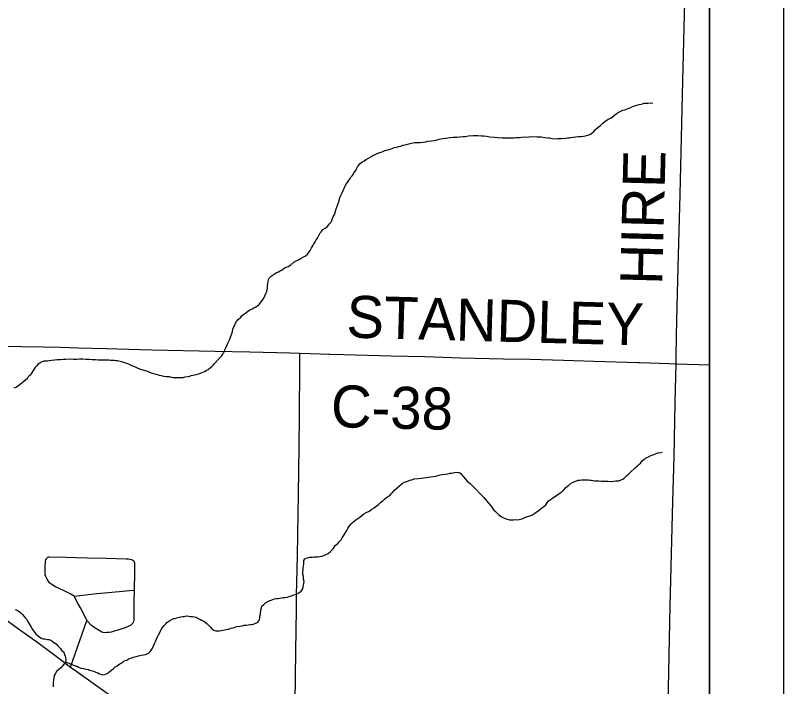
# Model space of a CAD drawing. Extents: x 0 to 34, y 0 to 22.
# Drawn here: x 29.379 to 30.417, y 16.904 to 17.811 of the extents above; entities that cross this region are included whole.
import ezdxf

# ---------------------------------------------------------------- set-up
doc = ezdxf.new("R2010")
doc.units = 0
for name, color, linetype in [('GM_X_City_Street', 7, 'Continuous'), ('GM_X_County_Road', 7, 'Continuous'), ('GM_X_County_Road_Text', 7, 'Continuous'), ('GM_X_Minor_River', 7, 'Continuous'), ('GM_X_Township_Road', 7, 'Continuous'), ('SH_Data', 7, 'Continuous')]:
    doc.layers.add(name, color=color, linetype=linetype)

msp = doc.modelspace()

# ---------------------------------------------------------------- linework, layer by layer
at = {"layer": 'GM_X_City_Street'}
for points in [[(29.4539, 16.9309), (29.4761, 16.9936), (29.4717, 17.0021), (29.4672, 17.0107), (29.4644, 17.0161), (29.459, 17.0266), (29.4533, 17.0298), (29.4461, 17.0334), (29.4388, 17.0369), (29.4338, 17.0393), (29.43, 17.0413), (29.4279, 17.0426), (29.4256, 17.0447), (29.4237, 17.0472), (29.4218, 17.0504), (29.4205, 17.0532), (29.4199, 17.0556), (29.4195, 17.0586), (29.4196, 17.0635), (29.4198, 17.068), (29.42, 17.0716), (29.4202, 17.074), (29.4207, 17.0757), (29.4213, 17.0769), (29.4219, 17.0777), (29.4226, 17.0784), (29.4235, 17.0791), (29.4244, 17.0795), (29.4254, 17.0796), (29.4475, 17.0793), (29.4762, 17.0785), (29.5022, 17.0778), (29.5292, 17.0771), (29.5318, 17.077), (29.5343, 17.0767), (29.5364, 17.0762), (29.5382, 17.0753), (29.5392, 17.0743), (29.5397, 17.0731), (29.5401, 17.0716), (29.5403, 17.0692), (29.5404, 17.065), (29.5403, 17.0566), (29.5402, 17.0508), (29.5399, 17.0431), (29.5398, 17.0379), (29.5397, 17.0346), (29.5397, 17.03), (29.5396, 17.0226), (29.5395, 17.0108), (29.5395, 17.004), (29.5394, 16.9965), (29.5392, 16.9934), (29.5387, 16.9916), (29.5379, 16.99), (29.5366, 16.9886), (29.5352, 16.9874), (29.5319, 16.9856), (29.5265, 16.9832), (29.5217, 16.9818), (29.519, 16.981), (29.5163, 16.9801), (29.5127, 16.9792), (29.509, 16.9781), (29.506, 16.9775), (29.5029, 16.9773), (29.4999, 16.9772), (29.4961, 16.9781), (29.4924, 16.9801), (29.4874, 16.9833), (29.4822, 16.987), (29.4761, 16.9936)], [(29.459, 17.0266), (29.4896, 17.0302), (29.5048, 17.0315), (29.5198, 17.033), (29.5334, 17.0341), (29.5397, 17.0346)]]:
    msp.add_lwpolyline(points, dxfattribs=at)
at = {"layer": 'GM_X_County_Road'}
for p, q in [((30.2714, 17.3404), (30.3167, 17.3391)), ((29.4539, 16.9309), (29.4623, 16.9248))]:
    msp.add_line(p, q, dxfattribs=at)
for points in [[(30.2714, 17.3404), (30.2716, 17.3482), (30.2721, 17.3787), (30.273, 17.4172), (30.2745, 17.4707), (30.2772, 17.5689), (30.2807, 17.7224), (30.283, 17.812), (30.2857, 17.9089), (30.2857, 17.9102), (30.2858, 17.9114), (30.287, 17.9667), (30.2885, 18.0102), (30.2894, 18.0531), (30.2902, 18.0898), (30.2911, 18.1296), (30.2925, 18.1812), (30.2935, 18.2184), (30.2939, 18.2503), (30.2938, 18.2543)], [(29.2614, 17.3664), (29.2894, 17.3655), (29.3043, 17.3651), (29.3229, 17.3648), (29.3362, 17.3646), (29.3679, 17.3641), (29.3883, 17.3637), (29.4168, 17.3634), (29.4405, 17.363), (29.4649, 17.3621), (29.502, 17.3612), (29.5635, 17.3593), (29.6487, 17.3575), (29.696, 17.3563), (29.7498, 17.355), (29.7636, 17.3547)], [(29.7636, 17.3547), (29.7912, 17.3538), (29.803, 17.3535), (29.804, 17.3535)], [(29.804, 17.3535), (29.8229, 17.3531), (29.8863, 17.3512), (29.9323, 17.3503), (29.9808, 17.3486), (30.0386, 17.3472), (30.0746, 17.3465), (30.1194, 17.3452), (30.1604, 17.3441), (30.2203, 17.3422), (30.2219, 17.3421), (30.2623, 17.3407), (30.2714, 17.3404)], [(29.2601, 17.0722), (29.2755, 17.0612), (29.298, 17.0446), (29.3449, 17.0108), (29.3616, 16.9987), (29.3837, 16.9826), (29.41, 16.9638), (29.4364, 16.9441), (29.4539, 16.9309)], [(29.4623, 16.9248), (29.5064, 16.8932), (29.5256, 16.8784), (29.5445, 16.8643), (29.5651, 16.8492), (29.5791, 16.839), (29.5943, 16.8281), (29.6104, 16.8163)]]:
    msp.add_lwpolyline(points, dxfattribs=at)
at = {"layer": 'GM_X_Minor_River'}
for points in [[(29.8653, 17.6232), (29.868, 17.6243), (29.8715, 17.6257), (29.8745, 17.6268), (29.8784, 17.6282), (29.8841, 17.6299), (29.888, 17.6313), (29.891, 17.6324), (29.8941, 17.633), (29.8972, 17.6337), (29.8998, 17.6344), (29.9025, 17.6355), (29.9052, 17.6361), (29.9075, 17.6365), (29.9106, 17.6375), (29.9144, 17.6382), (29.9182, 17.6392), (29.9231, 17.639), (29.9258, 17.6393), (29.9334, 17.6403), (29.9361, 17.6409), (29.9414, 17.6416), (29.9449, 17.6418), (29.9475, 17.6425), (29.9514, 17.6435), (29.9567, 17.6445), (29.9605, 17.6452), (29.9632, 17.6455), (29.9666, 17.6461), (29.9704, 17.6464), (29.9735, 17.6463), (29.9758, 17.6466), (29.9792, 17.6469), (29.9841, 17.6472), (29.9868, 17.6475), (29.991, 17.6481), (29.9975, 17.6487), (30.0036, 17.6485), (30.0081, 17.6484), (30.0119, 17.6482), (30.0153, 17.6478), (30.0198, 17.6469), (30.0259, 17.6463), (30.0308, 17.6458), (30.0365, 17.6456), (30.0411, 17.6455), (30.0464, 17.6453), (30.0502, 17.6456), (30.0528, 17.6455), (30.0551, 17.6458), (30.0578, 17.6461), (30.0605, 17.6461), (30.0627, 17.6464), (30.0662, 17.6467), (30.0704, 17.6465), (30.0749, 17.6472), (30.0833, 17.6469), (30.0893, 17.6468), (30.0943, 17.6458), (30.0981, 17.6457), (30.1007, 17.6453), (30.1041, 17.6448), (30.1075, 17.6443), (30.1113, 17.6446), (30.1166, 17.6448), (30.122, 17.645), (30.125, 17.6453), (30.1269, 17.6457), (30.1288, 17.646), (30.1395, 17.6472), (30.1414, 17.6471), (30.1433, 17.6475), (30.1464, 17.6478), (30.149, 17.6484), (30.1521, 17.6491), (30.1548, 17.6498), (30.1571, 17.6512), (30.1602, 17.6542), (30.1626, 17.6568), (30.1661, 17.6597), (30.1696, 17.6623), (30.1723, 17.6649), (30.1758, 17.6682), (30.1805, 17.6711), (30.1831, 17.6721), (30.1851, 17.6736), (30.1886, 17.6766), (30.1905, 17.678), (30.1932, 17.6798), (30.1967, 17.6816), (30.1998, 17.6827), (30.2021, 17.6834), (30.2044, 17.6841), (30.2067, 17.6852), (30.2094, 17.6858), (30.2125, 17.688), (30.2186, 17.6894), (30.2217, 17.6904), (30.2243, 17.6911), (30.2262, 17.6914), (30.2285, 17.6921)], [(30.2285, 17.6921), (30.2308, 17.6921), (30.2335, 17.6924), (30.2373, 17.6926), (30.24, 17.6925)], [(29.6714, 17.3798), (29.6722, 17.3821), (29.6726, 17.3844), (29.6731, 17.3866), (29.6739, 17.3893), (29.6751, 17.3915), (29.6764, 17.3941), (29.678, 17.3975), (29.6803, 17.4001), (29.6838, 17.4034), (29.6858, 17.4056), (29.6881, 17.4075), (29.6905, 17.4093), (29.6928, 17.4111), (29.6947, 17.4122), (29.6967, 17.4137), (29.699, 17.4148), (29.7013, 17.4158), (29.7036, 17.4169), (29.7055, 17.418), (29.7082, 17.4198), (29.7094, 17.4217), (29.7118, 17.4243), (29.715, 17.4288), (29.7178, 17.4355), (29.719, 17.4381), (29.7199, 17.4423), (29.72, 17.4461), (29.7205, 17.4484), (29.7209, 17.4514), (29.721, 17.4541), (29.7222, 17.4559), (29.7249, 17.4585), (29.7273, 17.4607), (29.73, 17.4625), (29.7319, 17.4636), (29.7346, 17.4647), (29.7369, 17.4658), (29.7396, 17.4672), (29.7427, 17.4698), (29.7477, 17.4719), (29.7512, 17.4741), (29.7555, 17.4774), (29.7594, 17.4799), (29.7624, 17.4814), (29.7655, 17.4832), (29.7686, 17.4846), (29.7705, 17.4857), (29.7737, 17.4883), (29.7752, 17.4901), (29.7776, 17.4935), (29.7792, 17.4968), (29.7812, 17.4995), (29.7824, 17.5025), (29.784, 17.5051), (29.7856, 17.5077), (29.7872, 17.5099), (29.7908, 17.517), (29.7928, 17.5189), (29.7944, 17.5215), (29.7979, 17.5237), (29.8006, 17.5255), (29.8021, 17.5274), (29.8037, 17.5292), (29.8053, 17.5311), (29.8065, 17.5337), (29.8077, 17.5367), (29.809, 17.5397), (29.8106, 17.5423), (29.8114, 17.5446), (29.8122, 17.5476), (29.8127, 17.5495), (29.8139, 17.5533), (29.8152, 17.557), (29.8164, 17.5604), (29.8172, 17.5634), (29.8185, 17.5668), (29.8205, 17.5713), (29.8221, 17.5743), (29.8233, 17.5773), (29.8246, 17.5803), (29.8258, 17.5826), (29.8278, 17.5852), (29.8293, 17.5874), (29.8313, 17.5904), (29.8325, 17.5923), (29.8341, 17.5941), (29.8353, 17.596), (29.8365, 17.5982), (29.8389, 17.6016), (29.8401, 17.6038), (29.8413, 17.6064), (29.8425, 17.6083), (29.8448, 17.6109), (29.8472, 17.6127), (29.8503, 17.6145), (29.8534, 17.6167), (29.8561, 17.6182), (29.8592, 17.62), (29.8622, 17.6218), (29.8653, 17.6232)], [(29.4029, 17.3298), (29.4049, 17.3328), (29.4061, 17.3347), (29.4073, 17.3365), (29.4092, 17.3384), (29.4108, 17.3402), (29.4135, 17.3424), (29.4154, 17.3431), (29.4185, 17.3442), (29.4204, 17.3445), (29.4227, 17.3444), (29.425, 17.3448), (29.4284, 17.3454), (29.4322, 17.3457), (29.436, 17.346), (29.4406, 17.3462), (29.4444, 17.3465), (29.4478, 17.3468), (29.4535, 17.347), (29.4581, 17.3468), (29.4623, 17.3467), (29.4661, 17.347), (29.4706, 17.3469), (29.4748, 17.3467), (29.479, 17.3466), (29.4831, 17.3461), (29.4877, 17.346), (29.4911, 17.3459), (29.4945, 17.3458), (29.4979, 17.3457), (29.5006, 17.3456), (29.5029, 17.3455), (29.5055, 17.3455), (29.5078, 17.3454), (29.5105, 17.3453), (29.5127, 17.3453), (29.5146, 17.3448), (29.5169, 17.3448), (29.5192, 17.3443), (29.5226, 17.3435), (29.5293, 17.3414), (29.5323, 17.3401), (29.5353, 17.3385), (29.5376, 17.3377), (29.5402, 17.3365), (29.5432, 17.3353), (29.5481, 17.3332), (29.5515, 17.3324), (29.5541, 17.3315), (29.556, 17.3307), (29.5579, 17.3303), (29.5605, 17.3291), (29.5643, 17.3278), (29.5677, 17.3266), (29.5711, 17.3257), (29.5737, 17.3252), (29.5763, 17.3244), (29.5793, 17.3236), (29.5835, 17.3231), (29.5854, 17.323), (29.5873, 17.323), (29.5899, 17.3225), (29.5926, 17.322), (29.5953, 17.322), (29.5979, 17.3219), (29.6006, 17.3218), (29.6032, 17.3217), (29.6059, 17.322), (29.6086, 17.3227), (29.6128, 17.3234), (29.6151, 17.3237), (29.617, 17.3244), (29.6193, 17.3251), (29.6212, 17.3254), (29.6235, 17.3261), (29.6265, 17.3268), (29.6292, 17.3278), (29.6315, 17.3285), (29.6338, 17.3296), (29.6358, 17.3303), (29.6377, 17.3318), (29.6396, 17.3325), (29.6427, 17.3354), (29.6447, 17.3369), (29.6466, 17.3387), (29.6482, 17.3406), (29.6541, 17.3469), (29.6564, 17.3491), (29.658, 17.3509), (29.6596, 17.3532), (29.6604, 17.3551), (29.6616, 17.3573), (29.6624, 17.3592), (29.6632, 17.3611), (29.6641, 17.3633), (29.6653, 17.3656), (29.6665, 17.3682), (29.6677, 17.3708), (29.6689, 17.3734), (29.6701, 17.3764), (29.6714, 17.3798)], [(29.378, 17.3077), (29.3799, 17.3088), (29.3822, 17.3103), (29.3841, 17.3117), (29.3911, 17.3168), (29.3935, 17.3191), (29.3962, 17.3213), (29.3978, 17.3239), (29.4005, 17.3261), (29.4017, 17.3279), (29.4029, 17.3298)], [(30.229, 17.2119), (30.2321, 17.2137), (30.2341, 17.2148), (30.2383, 17.2169), (30.2406, 17.2176), (30.2448, 17.2194), (30.2475, 17.2201), (30.2509, 17.2207), (30.2529, 17.2211)], [(29.9275, 17.1861), (29.9309, 17.1864), (29.9339, 17.1867), (29.9374, 17.1873), (29.9404, 17.1876), (29.9435, 17.1883), (29.9469, 17.1886), (29.953, 17.1903), (29.9557, 17.191), (29.9633, 17.1919), (29.9664, 17.1925), (29.9683, 17.1925), (29.9706, 17.1932), (29.9725, 17.1935), (29.9752, 17.1938), (29.9786, 17.1937), (29.9808, 17.1921), (29.9823, 17.1902), (29.9845, 17.1875), (29.9871, 17.1847), (29.9896, 17.182), (29.9933, 17.1788), (29.997, 17.1753), (30.0011, 17.171), (30.007, 17.1648), (30.0118, 17.1597), (30.0158, 17.155), (30.0188, 17.1515), (30.0213, 17.1484), (30.0235, 17.1456), (30.0253, 17.1429), (30.0276, 17.141), (30.0298, 17.1386), (30.0327, 17.1359), (30.0361, 17.1339), (30.0395, 17.1319), (30.0436, 17.1306), (30.0466, 17.1298), (30.0493, 17.1297), (30.0519, 17.1296), (30.055, 17.1299), (30.0573, 17.1298), (30.0595, 17.1301), (30.0615, 17.1305), (30.0637, 17.1312), (30.0664, 17.1322), (30.0695, 17.1336), (30.0741, 17.135), (30.0768, 17.1361), (30.0807, 17.1386), (30.0826, 17.1401), (30.0846, 17.1412), (30.0904, 17.146), (30.0927, 17.1478), (30.0954, 17.15), (30.0986, 17.1549), (30.1064, 17.1603), (30.1114, 17.1636), (30.1149, 17.1662), (30.1176, 17.168), (30.12, 17.1702), (30.1227, 17.1732), (30.1247, 17.175), (30.1266, 17.1765), (30.1286, 17.1783), (30.1316, 17.1801), (30.1336, 17.1808), (30.1363, 17.1819), (30.1393, 17.1833), (30.1416, 17.1833), (30.1439, 17.1836), (30.1477, 17.1838), (30.1504, 17.1838), (30.1534, 17.1837), (30.1553, 17.1832), (30.1572, 17.1832), (30.1591, 17.1827), (30.1613, 17.1823), (30.164, 17.1822), (30.167, 17.1821), (30.1701, 17.182), (30.1731, 17.182), (30.1761, 17.1819), (30.1795, 17.1818), (30.1845, 17.1816), (30.1875, 17.1819), (30.1902, 17.1822), (30.1921, 17.1825), (30.194, 17.1825), (30.1975, 17.1835), (30.1994, 17.1846), (30.2013, 17.1861), (30.2044, 17.189), (30.2076, 17.1916), (30.2099, 17.1938), (30.2165, 17.2001), (30.2189, 17.2023), (30.2212, 17.2045), (30.2236, 17.2063), (30.2259, 17.2093), (30.229, 17.2119)], [(29.7097, 16.997), (29.7097, 16.9996), (29.7102, 17.0023), (29.7102, 17.0042), (29.7107, 17.0061), (29.7107, 17.008), (29.7116, 17.0106), (29.7124, 17.0129), (29.7147, 17.0155), (29.7171, 17.0177), (29.7202, 17.0195), (29.7229, 17.0205), (29.7248, 17.0213), (29.7271, 17.0219), (29.7294, 17.023), (29.7321, 17.0233), (29.734, 17.0236), (29.7363, 17.024), (29.7385, 17.0243), (29.7412, 17.0246), (29.7435, 17.0249), (29.7462, 17.0252), (29.7546, 17.028), (29.7569, 17.0287), (29.7588, 17.0294), (29.7623, 17.0312), (29.7654, 17.0334), (29.7674, 17.0364), (29.7682, 17.0394), (29.7687, 17.0436), (29.7692, 17.0466), (29.7685, 17.0496), (29.7683, 17.0531), (29.7676, 17.0561), (29.7677, 17.0592), (29.7681, 17.0618), (29.7682, 17.0649), (29.7683, 17.0675), (29.7687, 17.0698), (29.7688, 17.0721), (29.7689, 17.0747), (29.7701, 17.077), (29.772, 17.0777), (29.7751, 17.0787), (29.777, 17.0791), (29.78, 17.0793), (29.7823, 17.0797), (29.7846, 17.0796), (29.7876, 17.0799), (29.7903, 17.0802), (29.793, 17.0805), (29.796, 17.0815), (29.7987, 17.083), (29.8018, 17.0844), (29.8049, 17.087), (29.8085, 17.0903), (29.8112, 17.0948), (29.8147, 17.0977), (29.8171, 17.1003), (29.8191, 17.1025), (29.8207, 17.1052), (29.8226, 17.1081), (29.827, 17.1152), (29.8282, 17.1179), (29.8298, 17.1201), (29.831, 17.122), (29.8326, 17.1242), (29.8346, 17.126), (29.8369, 17.1279), (29.8392, 17.1297), (29.8416, 17.1315), (29.8443, 17.1334), (29.847, 17.1356), (29.8501, 17.1378), (29.8532, 17.1396), (29.8563, 17.141), (29.8586, 17.1421), (29.8609, 17.1439), (29.864, 17.1457), (29.8667, 17.1483), (29.8695, 17.1505), (29.8726, 17.1531), (29.8757, 17.1553), (29.878, 17.1575), (29.8807, 17.1597), (29.8834, 17.1615), (29.8854, 17.163), (29.887, 17.1648), (29.8885, 17.1667), (29.8917, 17.17), (29.8948, 17.173), (29.8983, 17.1759), (29.9018, 17.1785), (29.9049, 17.1803), (29.9076, 17.1813), (29.9103, 17.1824), (29.9122, 17.1831), (29.9145, 17.1838), (29.9179, 17.1848), (29.9236, 17.1854), (29.9275, 17.1861)], [(29.3791, 17.0084), (29.3818, 17.0076), (29.3862, 17.0044), (29.3881, 17.0029), (29.3914, 16.9993), (29.3929, 16.9974), (29.3943, 16.9955), (29.3969, 16.9916), (29.398, 16.9893), (29.3994, 16.9869), (29.4009, 16.9846), (29.4019, 16.9827), (29.4041, 16.9796), (29.4056, 16.9773), (29.4071, 16.9753), (29.4097, 16.9733), (29.4126, 16.971), (29.4145, 16.9698), (29.4171, 16.9689), (29.419, 16.9689), (29.4209, 16.9685), (29.4228, 16.968), (29.4247, 16.968), (29.4273, 16.9671), (29.4292, 16.9659), (29.4325, 16.9636), (29.4344, 16.962), (29.4362, 16.96), (29.4381, 16.9581), (29.4403, 16.9561), (29.4418, 16.9538), (29.4447, 16.951), (29.4458, 16.9476), (29.4465, 16.9457), (29.4472, 16.9437), (29.4475, 16.9411), (29.447, 16.938), (29.4442, 16.9332), (29.4407, 16.9299), (29.4379, 16.9273), (29.4348, 16.9247), (29.4332, 16.9217), (29.432, 16.9195), (29.4316, 16.9164), (29.4311, 16.913), (29.4306, 16.9096), (29.4305, 16.9066), (29.4304, 16.9043)], [(29.447, 16.938), (29.4646, 16.9307), (29.4616, 16.9319), (29.4646, 16.9307), (29.468, 16.9295), (29.4714, 16.929), (29.4748, 16.9281), (29.4778, 16.9276), (29.4797, 16.9268), (29.4831, 16.9256), (29.485, 16.9252), (29.488, 16.9239), (29.491, 16.9231), (29.4932, 16.9219), (29.4963, 16.921), (29.4985, 16.9202), (29.5035, 16.9223), (29.5058, 16.9238), (29.5093, 16.9267), (29.5121, 16.9289), (29.5144, 16.9312), (29.5167, 16.9326), (29.5187, 16.9337), (29.5206, 16.9352), (29.5225, 16.9362), (29.5245, 16.9377), (29.5279, 16.9395), (29.5299, 16.9402), (29.5318, 16.9413), (29.5337, 16.9424), (29.5368, 16.9434), (29.5387, 16.9441), (29.5406, 16.9445), (29.5425, 16.9452), (29.5456, 16.9462), (29.5475, 16.9465), (29.5494, 16.9469), (29.5525, 16.9472), (29.5552, 16.9478), (29.5571, 16.9485), (29.559, 16.9496), (29.5617, 16.9522), (29.5637, 16.9548), (29.5657, 16.9582), (29.5665, 16.9604), (29.5674, 16.9627), (29.5686, 16.9653), (29.5702, 16.9687), (29.5714, 16.9717), (29.5726, 16.9743), (29.5767, 16.9822), (29.5782, 16.9841), (29.5798, 16.9863), (29.5826, 16.9893), (29.5841, 16.9911), (29.5865, 16.9926), (29.5899, 16.9947), (29.593, 16.9962), (29.5953, 16.9965), (29.5976, 16.9972), (29.6011, 16.9982), (29.603, 16.9985), (29.6049, 16.9989), (29.6072, 16.9992), (29.6106, 16.9999), (29.6136, 16.9994), (29.6155, 16.9993), (29.6186, 16.9992), (29.6212, 16.9988), (29.6235, 16.998), (29.6264, 16.9963), (29.6283, 16.9955), (29.6306, 16.9943), (29.6328, 16.9931), (29.6351, 16.9919), (29.638, 16.9895), (29.6402, 16.9872), (29.6428, 16.9848), (29.6447, 16.9825), (29.6473, 16.9805), (29.6499, 16.9797), (29.6533, 16.9796), (29.6552, 16.9799), (29.6571, 16.9803), (29.664, 16.9816), (29.6671, 16.9822), (29.6705, 16.9833), (29.6739, 16.9839), (29.6778, 16.9854), (29.6827, 16.986), (29.6858, 16.9866), (29.6885, 16.9873), (29.6911, 16.9876), (29.6938, 16.9879), (29.6965, 16.9882), (29.6988, 16.9885), (29.7011, 16.9889), (29.7037, 16.9899), (29.7064, 16.991), (29.7088, 16.9936), (29.7097, 16.997)]]:
    msp.add_lwpolyline(points, dxfattribs=at)
at = {"layer": 'GM_X_Township_Road'}
for points in [[(28.8021, 16.3696), (29.7483, 16.3505), (30.2361, 16.3375), (30.2681, 16.3359), (30.2735, 16.3357), (30.315, 16.335), (30.3167, 16.335), (30.3167, 20.9), (28.9104, 20.9)], [(29.7585, 16.7826), (29.7575, 16.7882), (29.7561, 16.7995), (29.7556, 16.8086), (29.7559, 16.8169), (29.7566, 16.8547), (29.7571, 16.8833), (29.758, 16.9516), (29.7585, 16.9815), (29.759, 17.0075), (29.7592, 17.0218), (29.7592, 17.0292), (29.7595, 17.0447), (29.7603, 17.0813), (29.7612, 17.1372), (29.7615, 17.1633), (29.7628, 17.2286), (29.7631, 17.2702), (29.7635, 17.3368), (29.7636, 17.3547)], [(30.2415, 16.3546), (30.2427, 16.3581), (30.2441, 16.3617), (30.2452, 16.3645), (30.2467, 16.3684), (30.2476, 16.3724), (30.2484, 16.3777), (30.2485, 16.3829), (30.249, 16.4185), (30.2509, 16.4925), (30.2518, 16.5354), (30.2539, 16.61), (30.2569, 16.7268), (30.2592, 16.8163), (30.2608, 16.8797), (30.2637, 17.0133), (30.267, 17.1544), (30.2688, 17.2147), (30.2692, 17.2396), (30.2702, 17.2887), (30.2714, 17.3404)]]:
    msp.add_lwpolyline(points, dxfattribs=at)
at = {"layer": 'SH_Data'}
for points in [[(23.4167, 21), (30.4167, 21), (30.4167, 14), (23.4167, 14)], [(23.5167, 20.9), (30.3167, 20.9), (30.3167, 14.1), (23.5167, 14.1)]]:
    msp.add_lwpolyline(points, close=True, dxfattribs=at)

# ---------------------------------------------------------------- texts
at = {"layer": 'GM_X_County_Road_Text'}
for s, rotation, p in [('HIRE', 88.5352, (30.2527, 17.4465)), ('STANDLEY', 358.4377, (29.8259, 17.3759)), ('C-38', 358.6533, (29.805, 17.2549))]:
    msp.add_text(s, height=0.05682, rotation=rotation, dxfattribs=at).set_placement(p)

doc.saveas('drawing.dxf')
